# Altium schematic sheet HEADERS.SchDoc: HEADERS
size A4; Author: Daniela Catanzaro; CompanyName: Arduino srl; DocumentNumber: ASX00055; SheetNumber: 8; SheetTotal: 10; RevAuthor: Daniela Catanzaro
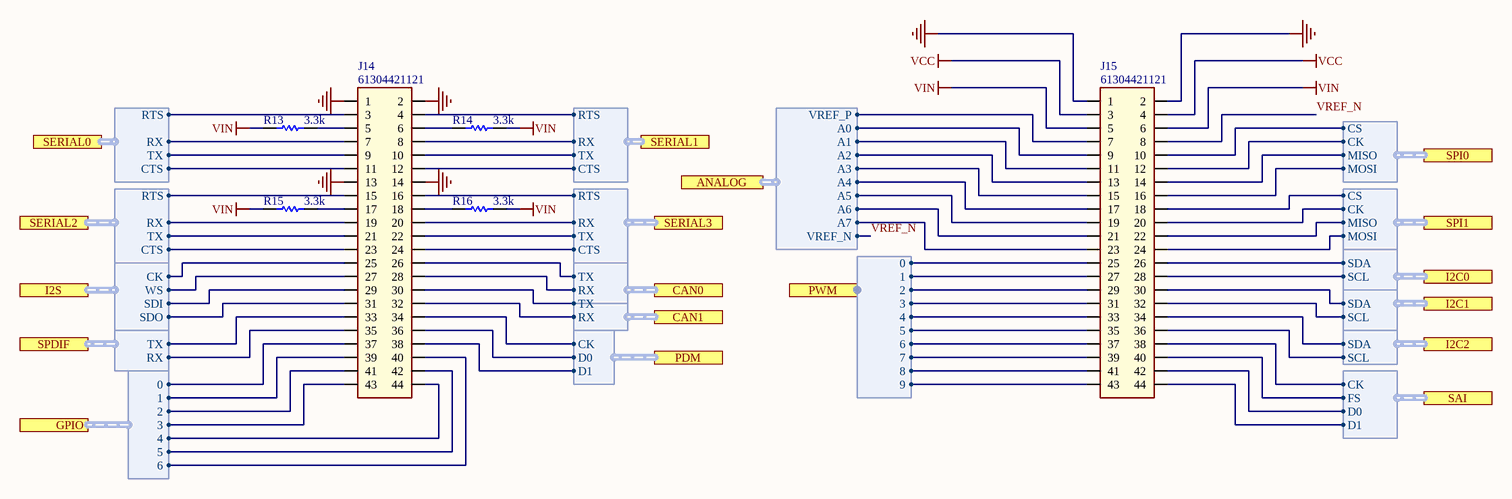
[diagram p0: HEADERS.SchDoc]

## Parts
J14  61304421121  [PIN HEADER 2.54mm VERT. 2x22POS]
J15  61304421121  [PIN HEADER 2.54mm VERT. 2x22POS]
R13  value 3.3k  [RES-0402]  (hidden comment: RC0402FR-073K3L)
R14  value 3.3k  [RES-0402]  (hidden comment: RC0402FR-073K3L)
R15  value 3.3k  [RES-0402]  (hidden comment: RC0402FR-073K3L)
R16  value 3.3k  [RES-0402]  (hidden comment: RC0402FR-073K3L)

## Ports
ANALOG (harness ANALOG), CAN0 (harness CAN), CAN1 (harness CAN), GPIO (harness GPIO), I2C0 (harness I2C), I2C1 (harness I2C), I2C2 (harness I2C), I2S (harness I2S), PDM (harness PDM), PWM (harness PWM), SAI (harness SAI), SERIAL0 (harness UART), SERIAL1 (harness UART), SERIAL2 (harness UART), SERIAL3 (harness UART), SPDIF (harness SPDIF), SPI0 (harness SPI), SPI1 (harness SPI)

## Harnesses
UART: TX, RX, CTS, RTS
I2C: SDA, SCL
CAN: RX, TX
SPDIF: TX, RX
SPI: CS, CK, MISO, MOSI
PWM: 0, 1, 2, 3, 4, 5, 6, 7, 8, 9
SAI: CK, FS, D0, D1
ANALOG: VREF_P, A0, A1, A2, A3, A7, A6, A5, A4, VREF_N
GPIO: 0, 1, 2, 3, 4, 5, 6
I2C: SCL, SDA
I2S: CK, SDI, SDO, WS
PDM: CK, D0, D1

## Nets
GND: J14.1 J14.2 J14.13 J14.14 J15.1 J15.2
VCC: J15.3 J15.4
VIN: J15.5 J15.6 R13.2 R14.1 R15.2 R16.1
VREF_N: J15.8 ; port ANALOG.VREF_N
NetJ14_3: J14.3 ; port SERIAL0.RTS
NetJ14_4: J14.4 ; port SERIAL1.RTS
NetJ14_5: J14.5 R13.1
NetJ14_6: J14.6 R14.2
NetJ14_7: J14.7 ; port SERIAL0.RX
NetJ14_8: J14.8 ; port SERIAL1.RX
NetJ14_9: J14.9 ; port SERIAL0.TX
NetJ14_10: J14.10 ; port SERIAL1.TX
NetJ14_11: J14.11 ; port SERIAL0.CTS
NetJ14_12: J14.12 ; port SERIAL1.CTS
NetJ14_15: J14.15 ; port SERIAL2.RTS
NetJ14_16: J14.16 ; port SERIAL3.RTS
NetJ14_17: J14.17 R15.1
NetJ14_18: J14.18 R16.2
NetJ14_19: J14.19 ; port SERIAL2.RX
NetJ14_20: J14.20 ; port SERIAL3.RX
NetJ14_21: J14.21 ; port SERIAL2.TX
NetJ14_22: J14.22 ; port SERIAL3.TX
NetJ14_23: J14.23 ; port SERIAL2.CTS
NetJ14_24: J14.24 ; port SERIAL3.CTS
NetJ14_25: J14.25 ; port I2S.CK
NetJ14_26: J14.26 ; port CAN0.TX
NetJ14_27: J14.27 ; port I2S.WS
NetJ14_28: J14.28 ; port CAN0.RX
NetJ14_29: J14.29 ; port I2S.SDI
NetJ14_30: J14.30 ; port CAN1.TX
NetJ14_31: J14.31 ; port I2S.SDO
NetJ14_32: J14.32 ; port CAN1.RX
NetJ14_34: J14.34 ; port PDM.CK
NetJ14_35: J14.35 ; port SPDIF.RX
NetJ14_36: J14.36 ; port PDM.D0
NetJ14_37: J14.37 ; port GPIO.0
NetJ14_38: J14.38 ; port PDM.D1
NetJ14_39: J14.39 ; port GPIO.1
NetJ14_40: J14.40 ; port GPIO.6
NetJ14_41: J14.41 ; port GPIO.2
NetJ14_42: J14.42 ; port GPIO.5
NetJ14_43: J14.43 ; port GPIO.3
NetJ14_44: J14.44 ; port GPIO.4
NetJ15_7: J15.7 ; port ANALOG.VREF_P
NetJ15_9: J15.9 ; port ANALOG.A0
NetJ15_10: J15.10 ; port SPI0.CS
NetJ15_11: J15.11 ; port ANALOG.A1
NetJ15_12: J15.12 ; port SPI0.CK
NetJ15_13: J15.13 ; port ANALOG.A2
NetJ15_14: J15.14 ; port SPI0.MISO
NetJ15_15: J15.15 ; port ANALOG.A3
NetJ15_16: J15.16 ; port SPI0.MOSI
NetJ15_17: J15.17 ; port ANALOG.A4
NetJ15_18: J15.18 ; port SPI1.CS
NetJ15_19: J15.19 ; port ANALOG.A5
NetJ15_20: J15.20 ; port SPI1.CK
NetJ15_21: J15.21 ; port ANALOG.A6
NetJ15_22: J15.22 ; port SPI1.MISO
NetJ15_23: J15.23 ; port ANALOG.A7
NetJ15_24: J15.24 ; port SPI1.MOSI
NetJ15_25: J15.25 ; port PWM.0
NetJ15_26: J15.26 ; port I2C0.SDA
NetJ15_27: J15.27 ; port PWM.1
NetJ15_28: J15.28 ; port I2C0.SCL
NetJ15_29: J15.29 ; port PWM.2
NetJ15_30: J15.30 ; port I2C1.SDA
NetJ15_31: J15.31 ; port PWM.3
NetJ15_32: J15.32 ; port I2C1.SCL
NetJ15_33: J15.33 ; port PWM.4
NetJ15_34: J15.34 ; port I2C2.SDA
NetJ15_35: J15.35 ; port PWM.5
NetJ15_36: J15.36 ; port I2C2.SCL
NetJ15_37: J15.37 ; port PWM.6
NetJ15_38: J15.38 ; port SAI.CK
NetJ15_39: J15.39 ; port PWM.7
NetJ15_40: J15.40 ; port SAI.FS
NetJ15_41: J15.41 ; port PWM.8
NetJ15_42: J15.42 ; port SAI.D0
NetJ15_43: J15.43 ; port PWM.9
NetJ15_44: J15.44 ; port SAI.D1

Not connected (* = marked no-connect by the designer): J14 33

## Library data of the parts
J14 J15 = J0356-A.7: HEADER TH 2.54mm VERT. MALE 2x22POS; Manufacturer: Wurth Elektronik; Code Arduino: J0356
R13-R16 = R0020-A.24: RES CHIP 0402 3k3 1% 1/16W; Manufacturer: YAGEO; Code Arduino: 2232; Power: 62.5mW; Temperature coefficient: 200ppm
